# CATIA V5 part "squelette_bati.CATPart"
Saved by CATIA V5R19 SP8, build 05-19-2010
Part number: squelette_bati
Publications: "Droite.1", "Droite.2", "Plan.1"
Bounding box of the stored display mesh (mm): x 83 to 83, y 0.085 to 251.964, z 66.284 to 88.354
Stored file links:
  G:\EU_thinkMotion\CFAO_2010\MMS_groupe3\MMS_groupe3\A reprendre\amenand\amenand\squelette_bati.CATPart
  F:\thinkmotion CFAO v12.1\essuie_glace.CATProduct
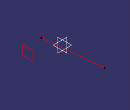
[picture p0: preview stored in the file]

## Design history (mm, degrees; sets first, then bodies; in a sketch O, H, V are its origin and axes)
Set1
  Plane1: linked copy from another document
  Point1: linked copy from another document
  Point2: linked copy from another document
Set2 "set géométrique.2"
  Line1: type PtPt, FirstPoint Point1, SecondPoint Point2
Body1 (main body)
